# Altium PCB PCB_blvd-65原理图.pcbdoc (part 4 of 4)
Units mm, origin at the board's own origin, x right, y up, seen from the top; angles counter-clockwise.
Board outline 317.5 x 107.96 mm, 2 copper layers (Top Layer, Bottom Layer); 180 components, 111 nets, 404 pads, 231 vias.
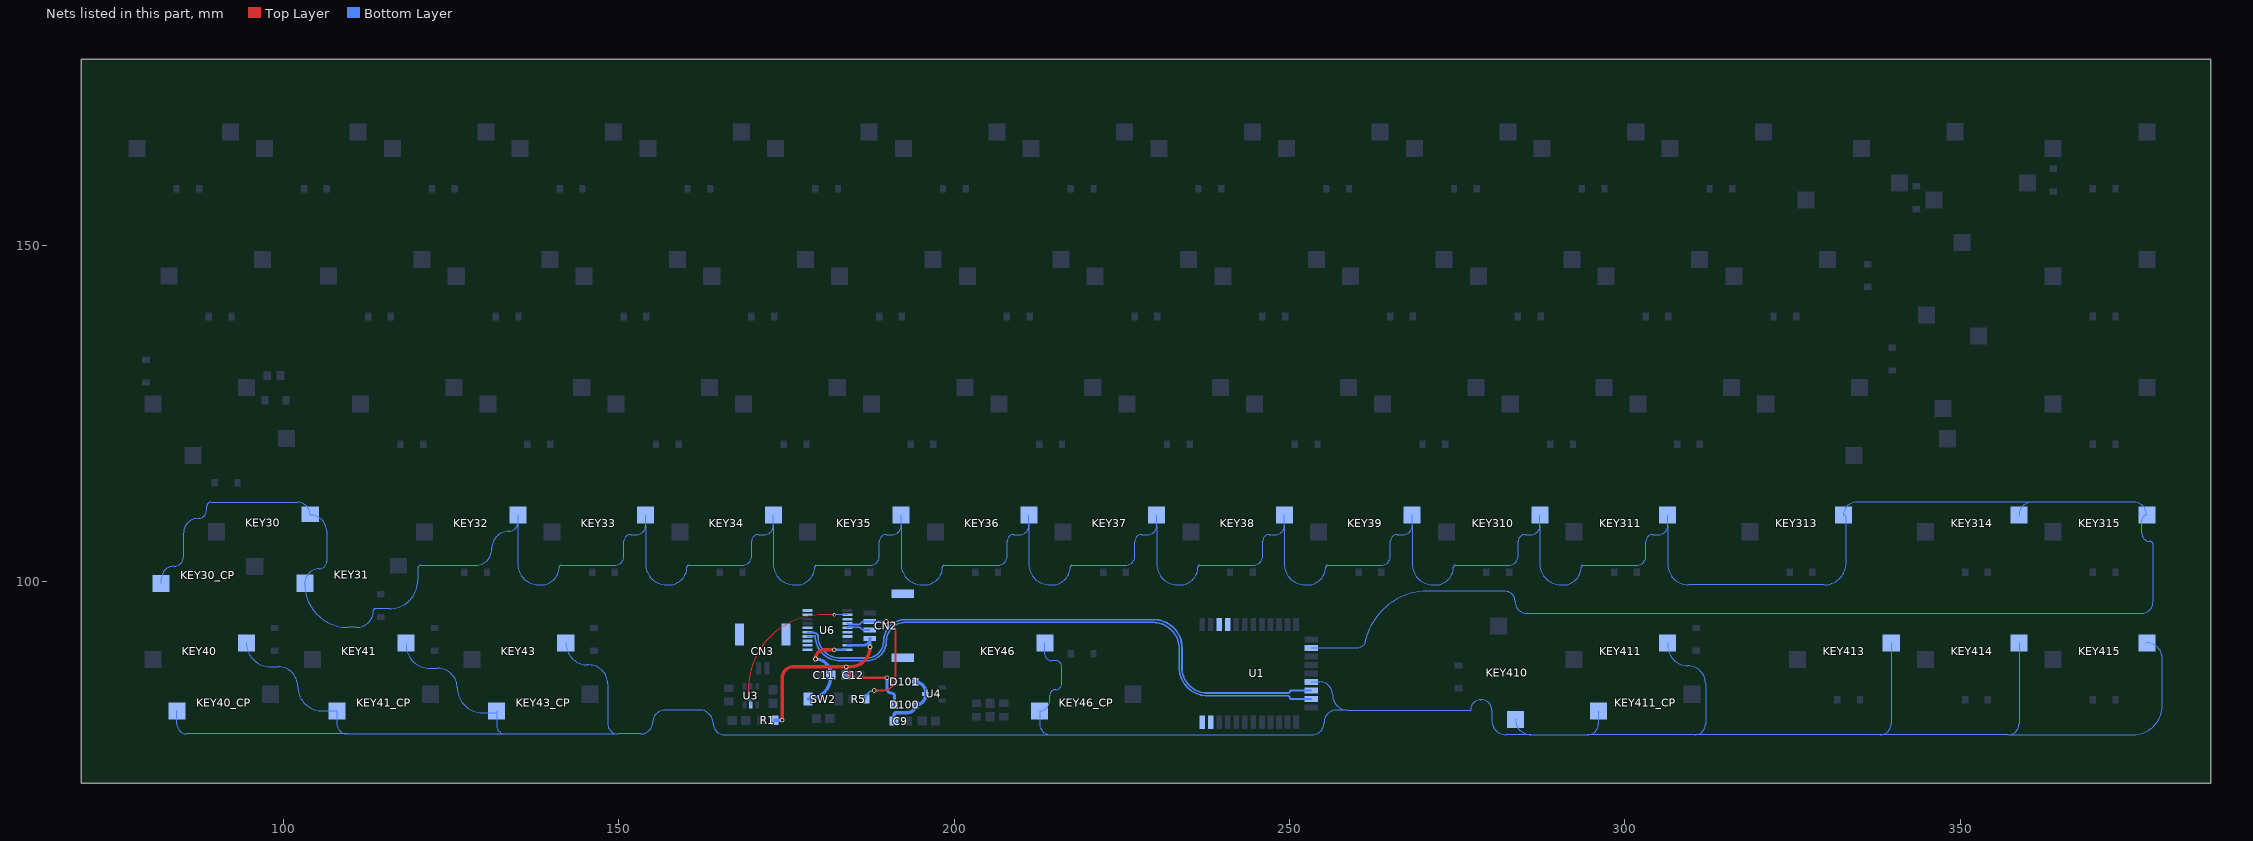
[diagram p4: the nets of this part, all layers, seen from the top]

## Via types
v1: diameter 0.5, hole 0.3, Top Layer to Bottom Layer, 198 vias
v2: diameter 0.7, hole 0.4, Top Layer to Bottom Layer, 33 vias

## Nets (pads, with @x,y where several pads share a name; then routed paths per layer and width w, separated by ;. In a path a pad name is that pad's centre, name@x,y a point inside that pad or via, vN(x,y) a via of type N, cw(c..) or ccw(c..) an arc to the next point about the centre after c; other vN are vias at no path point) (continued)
ROW3: KEY30.ROW KEY30_CP.ROW KEY31.ROW KEY32.ROW KEY33.ROW KEY34.ROW KEY35.ROW KEY36.ROW KEY37.ROW KEY38.ROW KEY39.ROW KEY310.ROW KEY311.ROW KEY313.ROW KEY314.ROW KEY315.ROW U1.14 | length 642.5
  Bottom Layer w0.1: KEY30_CP.ROW@81.756,99.665 81.756,100.298 cw(c83.693,100.298) 83.693,102.235 ccw(c83.693,103.632) 85.09,103.632 85.09,107.188 cw(c87.249,107.188) 87.249,109.347 ccw(c87.249,110.617) 88.519,110.617 88.519,111.125 cw(c89.154,111.125) 89.154,111.76 102.077,111.76 cw(c102.077,109.856) 103.981,109.856 cw(c103.981,107.411) 106.426,107.411 106.426,102.929 cw(c105.352,102.929) 105.352,101.854 ccw(c105.352,99.685) KEY31.ROW@103.183,99.685 103.183,99.51 ccw(c109.601,99.51) 109.601,93.091 110.871,93.091 ccw(c110.871,95.631) 113.411,95.631 cw(c113.665,95.631) 113.665,95.885 115.824,95.885 ccw(c115.824,100.076) 120.015,100.076 120.015,101.854 cw(c120.523,101.854) 120.523,102.362 128.651,102.362 ccw(c128.651,104.775) 131.064,104.775 131.064,104.902 cw(c133.604,104.902) 133.604,107.442 ccw(c133.604,108.771) KEY32.ROW@134.933,108.771 ; KEY32.ROW@134.933,109.845 KEY32.ROW@134.933,108.771 ; KEY33.ROW@153.983,109.845 153.983,108.263 ; KEY34.ROW@173.033,109.845 173.033,108.263 ; KEY35.ROW@192.083,109.845 192.083,108.263 ; KEY36.ROW@211.133,108.771 211.133,102.558 ccw(c214.25,102.558) 214.25,99.441 214.631,99.441 ccw(c214.631,102.108) 217.298,102.108 cw(c217.552,102.108) 217.552,102.362 225.553,102.362 ccw(c225.553,103.759) 226.95,103.759 226.95,105.918 cw(c227.966,105.918) 227.966,106.934 228.855,106.934 ccw(c228.855,108.263) 230.183,108.263 ; KEY36.ROW@211.133,109.845 211.133,108.263 cw(c209.804,108.263) 209.804,106.934 208.915,106.934 ccw(c208.915,105.918) 207.899,105.918 207.899,103.759 cw(c206.502,103.759) 206.502,102.362 198.501,102.362 ccw(c198.501,102.108) 198.247,102.108 cw(c195.58,102.108) 195.58,99.441 195.199,99.441 cw(c195.199,102.558) 192.083,102.558 192.083,108.263 ; KEY37.ROW@230.183,109.845 230.183,108.263 ; KEY38.ROW@249.233,109.845 249.233,108.263 ; U1.14@253.227,90.043 259.885,90.043 ccw(c259.885,91.778) 261.112,90.551 261.189,90.628 ; 261.189,90.628 cw(c270.638,88.9) 261.2,90.686 cw(c270.637,88.9) 261.266,91.008 ; 261.898,92.884 ccw(c270.637,88.9) 261.249,90.93 cw(c270.637,88.9) 264.808,96.534 cw(c270.637,88.9) 270.378,98.502 cw(c270.637,88.9) 270.637,98.505 282.067,98.505 cw(c282.067,96.901) 283.671,96.901 ccw(c285.369,96.901) 283.758,96.364 ccw(c285.369,96.901) 285.369,95.203 377.063,95.203 ccw(c377.063,96.901) 378.761,96.901 378.761,105.49 ccw(c378.333,105.49) 378.333,105.918 cw(c378.333,107.188) 377.063,107.188 377.063,109.093 cw(c377.825,109.093) KEY315.ROW@377.825,109.855 ccw(c375.92,109.855) 375.92,111.76 360.681,111.76 ; KEY39.ROW@268.283,109.845 268.283,108.263 ; KEY310.ROW@287.333,109.845 287.333,108.263 ; KEY311.ROW@306.383,109.845 306.383,108.263 ; KEY314.ROW@358.775,109.855 cw(c360.681,109.855) 360.681,111.76 ; KEY32.ROW@134.933,108.771 134.933,102.558 ccw(c138.049,102.558) 138.049,99.441 138.43,99.441 ccw(c138.43,102.108) 141.097,102.108 cw(c141.351,102.108) 141.351,102.362 149.352,102.362 ccw(c149.352,103.759) 150.749,103.759 150.749,105.918 cw(c151.765,105.918) 151.765,106.934 152.654,106.934 ccw(c152.654,108.263) 153.983,108.263 ; 153.983,108.263 153.983,102.558 ccw(c157.099,102.558) 157.099,99.441 157.48,99.441 ccw(c157.48,102.108) 160.147,102.108 cw(c160.401,102.108) 160.401,102.362 168.402,102.362 ccw(c168.402,103.759) 169.799,103.759 169.799,105.918 cw(c170.815,105.918) 170.815,106.934 171.704,106.934 ccw(c171.704,108.263) 173.033,108.263 ; 173.033,108.263 173.033,102.558 ccw(c176.149,102.558) 176.149,99.441 176.53,99.441 ccw(c176.53,102.108) 179.197,102.108 cw(c179.451,102.108) 179.451,102.362 187.452,102.362 ccw(c187.452,103.759) 188.849,103.759 188.849,105.918 cw(c189.865,105.918) 189.865,106.934 190.754,106.934 ccw(c190.754,108.263) 192.083,108.263 ; 230.183,108.263 230.183,102.558 ccw(c233.3,102.558) 233.3,99.441 233.681,99.441 ccw(c233.681,102.108) 236.348,102.108 cw(c236.602,102.108) 236.602,102.362 244.603,102.362 ccw(c244.603,103.759) 246,103.759 246,105.918 cw(c247.016,105.918) 247.016,106.934 247.905,106.934 ccw(c247.905,108.263) 249.233,108.263 ; 249.233,108.263 249.233,102.558 ccw(c252.35,102.558) 252.35,99.441 252.731,99.441 ccw(c252.731,102.108) 255.398,102.108 cw(c255.652,102.108) 255.652,102.362 263.653,102.362 ccw(c263.653,103.759) 265.05,103.759 265.05,105.918 cw(c266.066,105.918) 266.066,106.934 266.955,106.934 ccw(c266.955,108.263) 268.283,108.263 ; 268.283,108.263 268.283,102.558 ccw(c271.4,102.558) 271.4,99.441 271.781,99.441 ccw(c271.781,102.108) 274.448,102.108 cw(c274.702,102.108) 274.702,102.362 282.703,102.362 ccw(c282.703,103.759) 284.1,103.759 284.1,105.918 cw(c285.116,105.918) 285.116,106.934 286.005,106.934 ccw(c286.005,108.263) 287.333,108.263 ; 287.333,108.263 287.333,102.558 ccw(c290.45,102.558) 290.45,99.441 290.831,99.441 ccw(c290.831,102.108) 293.498,102.108 cw(c293.752,102.108) 293.752,102.362 301.753,102.362 ccw(c301.753,103.759) 303.15,103.759 303.15,105.918 cw(c304.166,105.918) 304.166,106.934 305.055,106.934 ccw(c305.055,108.263) 306.383,108.263 ; 306.383,108.263 306.383,102.558 ccw(c309.5,102.558) 309.5,99.441 329.692,99.441 ccw(c329.692,102.743) 332.994,102.743 332.994,109.442 ccw(c332.582,109.442) KEY313.ROW@332.582,109.855 cw(c334.487,109.855) 334.487,111.76 360.681,111.76
ROW4: KEY40.ROW KEY40_CP.ROW KEY41.ROW KEY41_CP.ROW KEY43.ROW KEY43_CP.ROW KEY46.ROW KEY46_CP.ROW KEY410.ROW KEY411.ROW KEY411_CP.ROW KEY413.ROW KEY414.ROW KEY415.ROW U1.18 | length 469.3
  Bottom Layer w0.1: KEY40_CP.ROW@84.138,80.646 ccw(c84.138,80.583) 84.074,80.583 84.074,78.74 ccw(c85.598,78.74) 85.598,77.216 109.474,77.216 ; KEY40.ROW@94.456,90.806 ccw(c98.013,90.806) 98.013,87.249 99.187,87.249 cw(c99.187,84.328) 102.108,84.328 ccw(c105.79,84.328) 105.79,80.646 KEY41_CP.ROW@107.95,80.646 107.95,78.74 ccw(c109.474,78.74) 109.474,77.216 ; KEY41.ROW@118.267,90.55 ccw(c121.824,90.55) 121.824,86.993 122.998,86.993 cw(c122.998,84.072) 125.919,84.072 ccw(c129.601,84.072) 129.601,80.39 KEY43_CP.ROW@131.761,80.39 ; KEY43_CP.ROW@131.763,80.646 131.763,78.486 ccw(c133.033,78.486) 133.033,77.216 ; KEY43.ROW@142.081,90.806 ccw(c145.384,90.806) 145.384,87.503 145.542,87.503 cw(c145.542,84.709) 148.336,84.709 148.336,78.74 ccw(c149.86,78.74) 149.86,77.216 ; KEY46.ROW@213.517,90.806 213.517,89.124 ccw(c214.503,89.124) 214.503,88.138 215.138,88.138 cw(c215.138,87.249) 216.027,87.249 216.027,84.709 cw(c215.138,84.709) 215.138,83.82 ccw(c215.138,82.931) 214.249,82.931 214.249,82.171 cw(c212.725,82.171) KEY46_CP.ROW@212.725,80.646 212.725,78.74 ccw(c214.376,78.74) 214.376,77.089 ; U1.18@253.227,84.963 254.509,84.963 cw(c254.509,83.058) 256.413,83.058 ccw(c258.699,83.058) 258.699,80.772 ; KEY410.ROW@283.686,79.376 ccw(c285.973,79.376) 285.973,77.089 ; KEY411_CP.ROW@296.067,80.646 296.067,78.74 cw(c294.416,78.74) 294.416,77.089 ; KEY411.ROW@306.387,90.806 306.387,90.361 ccw(c309.372,90.361) 309.372,87.376 cw(c309.372,84.709) 312.039,84.709 312.039,78.74 cw(c310.388,78.74) 310.388,77.089 ; KEY413.ROW@339.725,90.805 339.725,78.74 cw(c338.074,78.74) 338.074,77.089 ; KEY414.ROW@358.775,90.805 358.775,78.74 cw(c357.124,78.74) 357.124,77.089 ; KEY415.ROW@377.825,90.805 cw(c377.825,88.519) 380.111,88.519 380.111,81.407 cw(c375.793,81.407) 375.793,77.089 357.124,77.089 ; 109.474,77.216 133.033,77.216 ; 133.033,77.216 149.86,77.216 ; 149.86,77.216 153.289,77.216 ccw(c153.289,78.994) 155.067,78.994 cw(c156.845,78.994) 156.845,80.772 162.052,80.772 cw(c162.052,78.74) 164.084,78.74 ccw(c165.735,78.74) 165.735,77.089 214.376,77.089 ; 214.376,77.089 253.365,77.089 ccw(c253.365,78.867) 255.143,78.867 cw(c257.048,78.867) 257.048,80.772 258.699,80.772 ; 258.699,80.772 276.987,80.772 cw(c278.511,80.772) 278.511,82.296 278.638,82.296 cw(c278.638,80.772) 280.162,80.772 280.162,79.248 ccw(c282.321,79.248) 282.321,77.089 285.973,77.089 ; 285.973,77.089 294.416,77.089 ; 294.416,77.089 310.388,77.089 ; 310.388,77.089 338.074,77.089 ; 338.074,77.089 357.124,77.089
RXD: U1.20 U6.4 | length 88.3
  Bottom Layer w0.254: U6.4@178.101,91.735 178.975,91.735 179.097,91.857 179.224,91.857 cw(c179.224,91.794) 179.287,91.794 ccw(c182.943,91.794) 182.943,88.138 186.969,88.138 ccw(c186.969,91.059) 189.89,91.059 cw(c192.684,91.059) 192.684,93.853 229.616,93.853 cw(c229.616,89.916) 233.553,89.916 233.553,87.122 ccw(c237.769,87.122) 237.769,82.906 249.707,82.906 cw(c249.707,82.55) 250.063,82.55 ccw(c250.19,82.55) 250.19,82.423 U1.20@253.227,82.423
STBY: U3.5 U6.12 | length 23.7
  Top Layer w0.1: v1(169.291,82.423) 169.291,83.82 cw(c180.456,83.82) 180.456,94.985 v1(182.118,94.985)
  Bottom Layer w0.1: v1(169.291,82.423) cw(c169.291,82.042) 169.672,82.042 U3.5@169.672,81.531 ; v1(182.118,94.985) U6.12@184.104,94.985
TXD: U1.19 U6.5 | length 88.3
  Bottom Layer w0.254: U6.5@178.101,92.385 178.975,92.385 179.097,92.263 179.224,92.263 cw(c179.224,91.794) 179.693,91.794 ccw(c182.943,91.794) 182.943,88.544 186.969,88.544 ccw(c186.969,91.059) 189.484,91.059 cw(c192.684,91.059) 192.684,94.259 229.784,94.259 cw(c229.784,90.084) 233.959,90.084 233.959,87.122 ccw(c237.769,87.122) 237.769,83.312 249.809,83.312 ccw(c249.809,83.566) 250.063,83.566 cw(c250.19,83.566) 250.19,83.693 U1.19@253.227,83.693
UD+: CN2.2 R5.1 U6.14 | length 35.8
  Top Layer w0.254: v2(188.087,83.693) 189.357,83.693 ; 189.357,83.693 ccw(c189.357,85.598) 191.262,85.598 ; 189.357,83.693 ccw(c189.357,85.598) 191.262,85.598 ; 189.357,83.693 ccw(c189.357,85.598) 191.262,85.598 ; v2(189.865,93.98) cw(c189.865,92.583) 191.262,92.583 ; v2(189.865,93.98) cw(c189.865,92.583) 191.262,92.583 ; v2(189.865,93.98) cw(c189.865,92.583) 191.262,92.583 ; 191.262,85.598 191.262,92.583
  Bottom Layer w0.254: U6.14@184.104,93.685 184.104,93.638 184.193,93.548 185.919,93.548 186.351,93.98 CN2.2@187.428,93.98 v2(189.865,93.98) ; v2(188.087,83.693) v2@188.071,83.693 ; R5.1@186.801,82.423 cw(c188.071,82.423) v2@188.071,83.693 ; R5.1@186.801,82.423 cw(c188.071,82.423) v2@188.071,83.693 ; R5.1@186.801,82.423 cw(c188.071,82.423) v2@188.071,83.693
  other v1: 188.087,83.693 189.865,93.98
  other v2: 188.087,83.693
UD-: CN2.3 U6.15 | length 3.6
  Bottom Layer w0.254: U6.15@184.104,93.035 184.104,93.098 184.148,93.142 185.919,93.142 186.351,92.71 CN2.3@187.428,92.71
V33: C11.2 SW2.2 U6.20 | length 14.4
  Top Layer w0.5: v2(179.324,88.392) cw(c180.721,88.392) 180.721,89.789 v2(182.118,89.789)
  Bottom Layer w0.4: v2(182.118,89.789) U6.20@183.719,89.789
  Bottom Layer w0.5: SW2.2@178.217,82.423 ccw(c178.217,85.8) 181.594,85.8 C11.2@181.594,85.979 181.594,86.122 ccw(c179.324,86.122) v2(179.324,88.392)
VCC: C12.2 CN2.4 D100.2 R1.2 U6.19 | length 41.4
  Top Layer w0.4: v2(183.912,87.249) ccw(c185.563,87.249) 185.563,85.598 v2(189.992,85.598)
  Top Layer w0.5: v2(174.371,79.248) 174.371,85.598 cw(c176.022,85.598) 176.022,87.249 v2(183.912,87.249) 184.531,87.249 ccw(c184.531,90.17) v2(187.452,90.17)
  Bottom Layer w0.4: U6.19@184.098,90.435 186.423,90.435 ccw(c186.423,91.44) CN2.4@187.428,91.44 ; v2(189.992,85.598) 189.992,83.947 ccw(c190.627,83.947) 190.627,83.312 cw(c190.627,82.83) 191.109,82.83 D100.2@191.109,81.534
  Bottom Layer w0.5: R1.2@173.212,79.248 v2(174.371,79.248) ; C12.2@183.912,85.979 v2(183.912,87.249) ; CN2.4@187.428,91.44 cw(c187.428,91.415) 187.452,91.415 v2(187.452,90.17)
VIN: C9.2 D100.1 D101.1 U4.3 | length 10.1
  Bottom Layer w0.5: C9.2@191.024,79.121 191.024,80.026 cw(c191.389,80.026) 191.389,80.391 193.066,80.391 ccw(c193.066,81.534) D100.1@194.209,81.534 ccw(c194.209,83.067) 195.742,83.067 U4.3@195.742,83.185 195.742,83.43 ccw(c194.209,83.43) D101.1@194.209,84.963
"": CN2.5 CN2.6 CN3.3 CN3.4 U1.3 U1.4 U1.32 U1.33 U6.1 U6.2 U6.3 U6.6 U6.9 U6.10 U6.13 U6.16 U6.17

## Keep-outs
Board Outline Layer:
  lines w0.254 net "": 185.461,132.674 185.461,119.349 ccw(c185.86,119.349) 185.86,118.949 ccw(c185.86,119.349) 186.26,119.349 186.26,132.547 ; 233.763,113.628 233.763,100.303 cw(c233.363,100.303) 233.363,99.903 cw(c233.363,100.303) 232.963,100.303 232.963,113.501 ; 315.125,133.751 325.591,133.752 cw(c328.549,132.207) 331.508,133.751 332.575,133.751 ccw(c332.575,134.151) 332.975,134.151 ; 315.269,133.751 cw(c315.269,134.151) 314.869,134.151 ; 318.81,132.674 318.81,119.349 ccw(c319.21,119.349) 319.21,118.949 ccw(c319.21,119.349) 319.61,119.349 319.61,132.547 ; 319.888,132.951 326.127,132.947 cw(c328.549,132.207) 330.97,132.951 333.375,132.951 ccw(c333.375,133.351) 333.775,133.351 ; 320.01,132.947 ccw(c320.01,132.547) 319.61,132.547 ; 104.502,147.476 104.502,133.351 ccw(c104.902,133.351) 104.902,132.951 ; 104.502,147.476 cw(c104.902,147.476) 104.902,147.876 cw(c104.902,147.476) 105.302,147.476 ; 104.502,147.476 104.502,147.476 ; 104.898,132.947 108.86,132.947 ; 104.898,132.947 104.898,132.947 ; 104.902,132.951 104.902,132.951 ; 105.302,134.151 105.302,147.476 ; 105.302,134.151 105.302,134.151 ; 105.302,134.151 ccw(c105.702,134.151) 105.702,133.751 ; 105.302,147.476 105.302,147.476 ; 105.702,133.751 105.702,133.751 ; 105.719,133.751 105.719,133.751 ; 105.719,133.751 123.169,133.751 123.169,133.751 ccw(c123.169,134.151) 123.569,134.151 123.569,134.151 123.569,147.476 123.569,147.476 cw(c123.969,147.476) 123.969,147.876 cw(c123.969,147.476) 124.369,147.476 ; 108.86,132.947 cw(c108.86,132.547) 109.26,132.547 ; 108.86,132.947 108.86,132.947 ; 109.26,132.547 109.26,119.349 ccw(c109.66,119.349) 109.66,118.949 ccw(c109.66,119.349) 110.06,119.349 110.06,132.547 ; 109.26,132.547 109.26,132.547 ; 110.06,132.547 cw(c110.46,132.547) 110.46,132.947 ; 110.06,132.547 110.06,132.547 ; 110.46,132.947 127.91,132.947 ; 110.46,132.947 110.46,132.947 ; 118.663,114.301 cw(c119.063,114.301) 119.063,114.701 ; 118.663,114.301 118.663,114.301 ; 118.663,114.301 118.663,100.303 ccw(c119.063,100.303) 119.063,99.903 ccw(c119.063,100.303) 119.463,100.303 119.462,113.501 ; 119.063,114.701 138.512,114.701 157.562,114.701 176.612,114.701 ; 119.063,114.701 119.063,114.701 ; 119.462,113.501 119.463,113.501 ; 119.463,113.501 cw(c119.863,113.501) 119.863,113.901 ; 119.863,113.901 119.862,113.901 ; 119.863,113.901 137.312,113.901 ; 119.862,113.901 119.863,113.901 ; 124.369,134.151 124.369,147.476 ; 124.369,134.151 ccw(c124.769,134.151) 124.769,133.751 ; 124.369,134.151 124.369,134.151 ; 124.369,147.476 124.369,147.476 ; 124.769,133.751 124.769,133.751 ; 124.769,133.751 124.769,133.751 ; 124.769,133.751 142.219,133.751 142.219,133.751 ccw(c142.219,134.151) 142.619,134.151 ; 127.91,132.947 cw(c127.91,132.547) 128.31,132.547 ; 127.91,132.947 127.91,132.947 ; 128.31,132.547 128.31,119.349 ccw(c128.71,119.349) 128.71,118.949 ccw(c128.71,119.349) 129.11,119.349 129.11,132.547 ; 128.31,132.547 128.31,132.547 ; 129.11,132.547 cw(c129.51,132.547) 129.51,132.947 ; 129.11,132.547 129.11,132.547 ; 129.51,132.947 146.96,132.947 ; 129.51,132.947 129.51,132.947 ; 137.312,113.901 137.312,113.901 ; 137.312,113.901 cw(c137.312,113.501) 137.712,113.501 ; 137.712,113.501 137.712,113.501 ; 137.712,113.501 137.712,100.303 ccw(c138.112,100.303) 138.112,99.903 ccw(c138.112,100.303) 138.512,100.303 138.512,113.501 ; 138.512,113.501 138.512,113.501 ; 138.512,113.501 cw(c138.912,113.501) 138.912,113.901 156.362,113.901 cw(c156.362,113.501) 156.762,113.501 ; 142.619,134.151 142.619,134.151 ; 142.619,134.151 142.619,147.476 ; 142.619,147.476 142.619,147.476 ; 142.619,147.476 cw(c143.019,147.476) 143.019,147.876 cw(c143.019,147.476) 143.419,147.476 ; 143.419,134.151 143.419,147.476 ; 143.419,134.151 143.419,134.151 ; 143.419,134.151 ccw(c143.819,134.151) 143.819,133.751 161.269,133.751 ; 143.419,147.476 143.419,147.476 ; 146.96,132.947 cw(c146.96,132.547) 147.36,132.547 ; 146.96,132.947 146.96,132.947 ; 147.36,132.547 147.36,119.349 ccw(c147.76,119.349) 147.76,118.949 ccw(c147.76,119.349) 148.16,119.349 148.16,132.547 148.16,132.547 cw(c148.56,132.547) 148.56,132.947 ; 147.36,132.547 147.36,132.547 ; 148.56,132.947 166.01,132.947 ; 148.56,132.947 148.56,132.947 ; 156.762,113.501 156.762,113.501 ; 156.762,113.501 156.762,100.303 ccw(c157.162,100.303) 157.162,99.903 ccw(c157.162,100.303) 157.562,100.303 157.562,113.501 ; 157.562,113.501 157.562,113.501 ; 157.562,113.501 cw(c157.962,113.501) 157.962,113.901 ; 157.962,113.901 157.962,113.901 ; 157.962,113.901 175.412,113.901 ; 161.269,133.751 161.269,133.751 ; 161.269,133.751 ccw(c161.269,134.151) 161.669,134.151 ; 161.669,134.151 161.669,134.151 ; 161.669,134.151 161.669,134.151 ; 161.669,134.151 161.669,147.476 ; 161.669,147.476 161.669,147.476 ; 161.669,147.476 161.669,147.476 ; 161.669,147.476 cw(c162.069,147.476) 162.069,147.876 cw(c162.069,147.476) 162.469,147.476 ; 162.469,134.151 162.469,147.476 ; 162.469,134.151 162.469,134.151 ; 162.469,134.151 ccw(c162.869,134.151) 162.869,133.751 162.869,133.751 180.319,133.751 ccw(c180.319,134.151) 180.719,134.151 ; 162.469,147.476 162.469,147.476 ; 166.01,132.947 cw(c166.01,132.547) 166.41,132.547 ; 166.01,132.947 166.01,132.947 ; 166.41,132.547 166.41,119.349 ccw(c166.81,119.349) 166.81,118.949 ccw(c166.81,119.349) 167.21,119.349 167.21,132.547 ; 166.41,132.547 166.41,132.547 ; 167.21,132.547 cw(c167.61,132.547) 167.61,132.947 ; 167.21,132.547 167.21,132.547 ; 167.61,132.947 185.06,132.947 ; 167.61,132.947 167.61,132.947 ; 175.412,113.901 175.412,113.901 ; 175.412,113.901 cw(c175.412,113.501) 175.812,113.501 ; 175.412,113.901 175.412,113.901 ; 175.812,113.501 175.812,113.501 ; 175.812,113.501 175.812,100.303 ccw(c176.212,100.303) 176.212,99.903 ccw(c176.212,100.303) 176.612,100.303 176.612,113.501 ; 176.612,113.501 176.612,113.501 ; 176.612,113.501 cw(c177.012,113.501) 177.012,113.901 ; 176.613,114.701 195.663,114.701 214.713,114.701 233.763,114.701 252.813,114.701 271.863,114.701 290.913,114.701 309.436,114.701 cw(c309.436,114.301) 309.836,114.301 309.836,100.303 cw(c309.436,100.303) 309.436,99.903 cw(c309.436,100.303) 309.036,100.303 309.036,113.501 ccw(c308.636,113.501) 308.636,113.901 291.313,113.901 ; 176.613,114.701 176.612,114.701 ; 177.012,113.901 177.012,113.901 ; 177.012,113.901 194.463,113.901 ; 177.012,113.901 177.012,113.901 ; 180.719,134.151 180.719,134.151 ; 180.719,134.151 180.719,147.476 ; 180.719,147.476 180.719,147.476 ; 180.719,147.476 cw(c181.119,147.476) 181.119,147.876 cw(c181.119,147.476) 181.519,147.476 ; 181.519,134.151 181.519,147.476 ; 181.519,134.151 181.519,134.151 ; 181.519,134.151 ccw(c181.919,134.151) 181.919,133.751 ; 181.519,147.476 181.519,147.476 ; 181.919,133.751 181.919,133.751 ; 181.919,133.751 199.369,133.751 ; 185.061,132.947 cw(c185.061,132.547) 185.461,132.547 ; 185.061,132.947 185.06,132.947 ; 185.461,132.547 185.461,132.547 ; 186.26,132.547 cw(c186.66,132.547) 186.66,132.947 ; 186.26,132.547 186.26,132.547 ; 186.66,132.947 204.11,132.947 ; 186.66,132.947 186.66,132.947 ; 194.463,113.901 194.463,113.901 ; 194.463,113.901 cw(c194.463,113.501) 194.863,113.501 ; 194.863,113.501 194.863,113.501 ; 194.863,113.501 194.863,100.303 ccw(c195.263,100.303) 195.263,99.903 ccw(c195.263,100.303) 195.663,100.303 195.663,113.501 ; 195.663,113.501 195.663,113.501 ; 195.663,113.501 cw(c196.063,113.501) 196.063,113.901 213.513,113.901 cw(c213.513,113.501) 213.913,113.501 ; 199.369,133.751 ccw(c199.369,134.151) 199.769,134.151 ; 199.369,133.751 199.369,133.751 ; 199.769,134.151 199.769,134.151 ; 199.769,134.151 199.769,147.476 ; 199.769,147.476 199.769,147.476 ; 199.769,147.476 cw(c200.169,147.476) 200.169,147.876 cw(c200.169,147.476) 200.569,147.476 ; 200.569,134.151 200.569,147.476 ; 200.569,134.151 200.569,134.151 ; 200.569,134.151 ccw(c200.969,134.151) 200.969,133.751 ; 200.569,147.476 200.569,147.476 ; 200.969,133.751 218.419,133.751 ; 200.969,133.751 200.969,133.751 ; 204.11,132.947 cw(c204.11,132.547) 204.51,132.547 ; 204.11,132.947 204.11,132.947 ; 204.51,132.547 204.51,119.349 ccw(c204.91,119.349) 204.91,118.949 ccw(c204.91,119.349) 205.31,119.349 205.31,132.547 ; 204.51,132.547 204.51,132.547 ; 205.31,132.547 cw(c205.71,132.547) 205.71,132.947 ; 205.31,132.547 205.31,132.547 ; 205.71,132.947 223.16,132.947 ; 205.71,132.947 205.71,132.947 ; 213.913,113.501 213.913,113.501 ; 213.913,113.501 213.913,100.303 ccw(c214.313,100.303) 214.313,99.903 ccw(c214.313,100.303) 214.713,100.303 214.713,113.501 ; 214.713,113.501 214.713,113.501 ; 214.713,113.501 cw(c215.113,113.501) 215.113,113.901 ; 215.113,113.901 215.113,113.901 ; 215.113,113.901 232.563,113.901 ; 218.419,133.751 218.419,133.751 ; 218.419,133.751 ccw(c218.419,134.151) 218.819,134.151 ; 218.819,134.151 218.819,134.151 ; 218.819,134.151 218.819,147.476 ; 218.819,147.476 218.819,147.476 ; 218.819,147.476 cw(c219.219,147.476) 219.219,147.876 cw(c219.219,147.476) 219.619,147.476 ; 219.619,134.151 219.619,147.476 ; 219.619,134.151 ccw(c220.019,134.151) 220.019,133.751 ; 219.619,134.151 219.619,134.151 ; 219.619,147.476 219.619,147.476 ; 219.619,147.476 219.619,147.476 ; 220.019,133.751 220.019,133.751 ; 220.019,133.751 237.469,133.751 ccw(c237.469,134.151) 237.869,134.151 ; 223.16,132.947 cw(c223.16,132.547) 223.56,132.547 ; 223.16,132.947 223.16,132.947 ; 223.56,132.547 223.56,119.349 ccw(c223.96,119.349) 223.96,118.949 ccw(c223.96,119.349) 224.36,119.349 224.36,132.547 ; 223.56,132.547 223.56,132.547 ; 224.36,132.547 cw(c224.76,132.547) 224.76,132.947 ; 224.36,132.547 224.36,132.547 ; 224.76,132.947 242.21,132.947 ; 224.76,132.947 224.76,132.947 ; 232.563,113.901 232.563,113.901 ; 232.563,113.901 cw(c232.563,113.501) 232.963,113.501 ; 232.563,113.901 232.563,113.901 ; 232.963,113.501 232.963,113.501 ; 233.763,113.501 233.763,113.501 ; 233.763,113.501 cw(c234.163,113.501) 234.163,113.901 ; 234.163,113.901 234.163,113.901 ; 234.163,113.901 251.613,113.901 ; 234.163,113.901 234.163,113.901 ; 237.869,134.151 237.869,134.151 ; 237.869,134.151 237.869,147.476 ; 237.869,147.476 237.869,147.476 ; 237.869,147.476 cw(c238.269,147.476) 238.269,147.876 cw(c238.269,147.476) 238.669,147.476 238.669,147.476 238.669,134.151 238.669,134.151 ccw(c239.069,134.151) 239.069,133.751 ; 239.069,133.751 239.069,133.751 ; 239.069,133.751 256.519,133.751 ; 242.21,132.947 cw(c242.21,132.547) 242.61,132.547 ; 242.21,132.947 242.21,132.947 ; 242.61,132.547 242.61,119.349 ccw(c243.01,119.349) 243.01,118.949 ccw(c243.01,119.349) 243.41,119.349 243.41,132.547 ; 242.61,132.547 242.61,132.547 ; 243.41,132.547 cw(c243.81,132.547) 243.81,132.947 ; 243.41,132.547 243.41,132.547 ; 243.81,132.947 261.26,132.947 ; 243.81,132.947 243.81,132.947 ; 251.613,113.901 251.613,113.901 ; 251.613,113.901 cw(c251.613,113.501) 252.013,113.501 ; 252.013,113.501 252.013,113.501 ; 252.013,113.501 252.013,100.303 ccw(c252.413,100.303) 252.413,99.903 ccw(c252.413,100.303) 252.813,100.303 252.813,113.501 ; 252.813,113.501 252.813,113.501 ; 252.813,113.501 cw(c253.213,113.501) 253.213,113.901 ; 252.813,113.501 252.813,113.501 ; 253.213,113.901 253.213,113.901 ; 253.213,113.901 270.663,113.901 cw(c270.663,113.501) 271.063,113.501 ; 253.213,113.901 253.213,113.901 ; 256.519,133.751 256.519,133.751 ; 256.519,133.751 ccw(c256.519,134.151) 256.919,134.151 ; 256.919,134.151 256.919,134.151 ; 256.919,134.151 256.919,134.151 ; 256.919,134.151 256.919,147.476 ; 256.919,147.476 256.919,147.476 ; 256.919,147.476 256.919,147.476 ; 256.919,147.476 cw(c257.319,147.476) 257.319,147.876 cw(c257.319,147.476) 257.719,147.476 ; 257.719,134.151 257.719,147.476 ; 257.719,134.151 257.719,134.151 ; 257.719,134.151 ccw(c258.119,134.151) 258.119,133.751 ; 257.719,147.476 257.719,147.476 ; 258.119,133.751 258.119,133.751 ; 258.119,133.751 275.569,133.751 275.569,133.751 ccw(c275.569,134.151) 275.969,134.151 275.969,134.151 275.969,147.476 275.969,147.476 cw(c276.369,147.476) 276.369,147.876 cw(c276.369,147.476) 276.769,147.476 ; 261.26,132.947 cw(c261.26,132.547) 261.66,132.547 ; 261.26,132.947 261.26,132.947 ; 261.66,132.547 261.66,119.349 ccw(c262.06,119.349) 262.06,118.949 ccw(c262.06,119.349) 262.46,119.349 262.46,132.547 ; 261.66,132.547 261.66,132.547 ; 262.46,132.547 cw(c262.86,132.547) 262.86,132.947 ; 262.46,132.547 262.46,132.547 ; 262.86,132.947 280.71,132.947 280.71,119.349 ccw(c281.11,119.349) 281.11,118.949 ccw(c281.11,119.349) 281.51,119.349 281.51,132.947 299.36,132.947 ; 262.86,132.947 262.86,132.947 ; 271.063,113.501 271.063,113.501 ; 271.063,113.501 271.063,100.303 ccw(c271.463,100.303) 271.463,99.903 ccw(c271.463,100.303) 271.863,100.303 271.863,113.501 ; 271.863,113.501 271.863,113.501 ; 271.863,113.501 cw(c272.263,113.501) 272.263,113.901 ; 272.263,113.901 272.263,113.901 ; 272.263,113.901 289.713,113.901 ; 276.769,134.151 276.769,147.476 ; 276.769,134.151 ccw(c277.169,134.151) 277.169,133.751 ; 276.769,134.151 276.769,134.151 ; 276.769,147.476 276.769,147.476 ; 276.769,147.476 276.769,147.476 ; 277.169,133.751 277.169,133.751 ; 277.169,133.751 294.619,133.751 294.619,133.751 ccw(c294.619,134.151) 295.019,134.151 ; 289.713,113.901 289.713,113.901 ; 289.713,113.901 cw(c289.713,113.501) 290.113,113.501 ; 289.713,113.901 289.713,113.901 ; 290.113,113.501 290.113,113.501 ; 290.113,113.501 290.113,100.303 ccw(c290.513,100.303) 290.513,99.903 ccw(c290.513,100.303) 290.913,100.303 290.913,113.501 ; 290.113,113.501 290.113,113.501 ; 290.913,113.501 290.913,113.501 ; 290.913,113.501 cw(c291.313,113.501) 291.313,113.901 ; 291.313,113.901 291.313,113.901 ; 295.019,134.151 295.019,134.151 ; 295.019,134.151 295.019,147.476 ; 295.019,147.476 295.019,147.476 ; 295.019,147.476 cw(c295.419,147.476) 295.419,147.876 cw(c295.419,147.476) 295.819,147.476 ; 295.819,134.151 295.819,147.476 ; 295.819,134.151 295.819,134.151 ; 295.819,134.151 ccw(c296.219,134.151) 296.219,133.751 313.669,133.751 ; 295.819,147.476 295.819,147.476 ; 299.36,132.947 cw(c299.36,132.547) 299.76,132.547 ; 299.36,132.947 299.36,132.947 ; 299.76,132.547 299.76,119.349 ccw(c300.16,119.349) 300.16,118.949 ccw(c300.16,119.349) 300.56,119.349 300.56,132.547 ; 299.76,132.547 299.76,132.547 ; 300.56,132.547 cw(c300.96,132.547) 300.96,132.947 ; 300.56,132.547 300.56,132.547 ; 300.96,132.947 318.41,132.947 ; 300.96,132.947 300.96,132.947 ; 313.669,133.751 313.669,133.751 ; 313.669,133.751 ccw(c313.669,134.151) 314.069,134.151 ; 314.069,134.151 314.069,134.151 ; 314.069,134.151 314.069,134.151 ; 314.069,134.151 314.069,147.476 ; 314.069,147.476 314.069,147.476 ; 314.069,147.476 cw(c314.469,147.476) 314.469,147.876 cw(c314.469,147.476) 314.869,147.476 ; 314.869,134.151 314.869,147.476 ; 314.869,134.151 314.869,134.151 ; 314.869,147.476 314.869,147.476 ; 318.41,132.947 cw(c318.41,132.547) 318.81,132.547 ; 318.41,132.947 318.41,132.947 ; 318.81,132.547 318.81,132.547 ; 319.61,132.547 319.61,132.547 ; 332.975,134.151 332.975,134.151 ; 332.975,134.151 332.975,147.476 ; 332.975,147.476 332.975,147.476 ; 332.975,147.476 cw(c333.375,147.476) 333.375,147.876 cw(c333.375,147.476) 333.775,147.476 ; 333.775,133.351 333.775,134.151 333.775,147.476 ; 333.775,133.351 333.775,133.351 ; 333.775,147.476 333.775,147.476 ; 76.701,79.2 76.701,168.45 cw(c79.201,168.45) 79.201,170.95 378,170.95 cw(c378,168.45) 380.5,168.45 380.5,79.2 cw(c378,79.2) 378,76.7 79.201,76.7 cw(c79.201,79.2) 76.701,79.2

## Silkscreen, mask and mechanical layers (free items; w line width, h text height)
Bottom Silkscreen Layer:
  text "G" at 195.961,95.943 h1.31
  text "D+" at 196.542,93.916 h1.3
  text "D-" at 196.542,92.138 h1.3
  text "V" at 195.961,90.101 h1.31
Mech6:
  drawing of 523 lines, arcs and shapes, not listed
